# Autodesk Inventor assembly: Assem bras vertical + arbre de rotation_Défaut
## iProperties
Shininess: 64.0
Length Units: 11269
Angle Units: 11279
Time Units: 11290
Mass Units: 11283
Length Display Precision: 3
Angle Display Precision: 2
Compacted: True
Created: 2006-11
Part Number: Assem bras vertical + arbre de rotation_Défaut
Document SubType Name: Assembly
Designer: profs_sti
Density: 0.0
Volumn: 0.0
Area: 0.0
PropertySet Name: Model Information
Control State: 0
Master: False
Checked Out: False
Author: profs_sti
